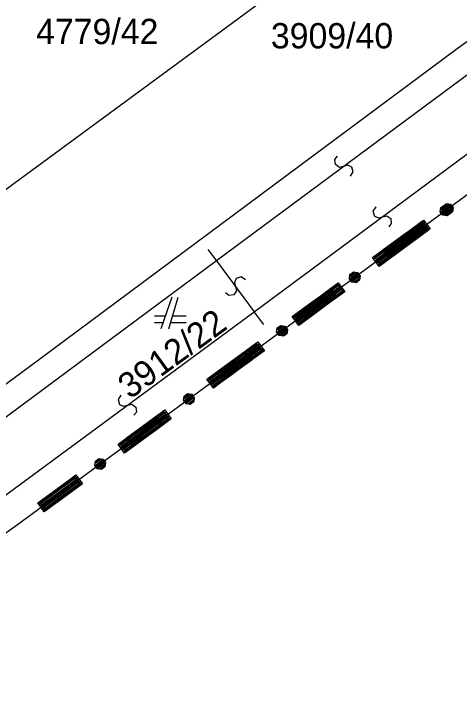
# Model space of a CAD drawing. Extents: x -266179 to -264727, y -1243225 to -1241702.
# Drawn here: x -265199.76 to -265171.61, y -1242850.11 to -1242805.99 of the extents above; entities that cross this region are included whole.
import ezdxf

# ---------------------------------------------------------------- set-up
doc = ezdxf.new("R2010")
doc.units = 0
for name, color, linetype in [('Vrstva 1', 7, 'Continuous'), ('Vrstva 19', 7, 'Continuous'), ('Vrstva 2', 7, 'Continuous'), ('Vrstva 21', 7, 'Continuous')]:
    doc.layers.add(name, color=color, linetype=linetype)

msp = doc.modelspace()

# ---------------------------------------------------------------- linework, layer by layer
at = {"layer": 'Vrstva 1'}
for p, q in [((-265203.44, -1242819.41), (-265176.4, -1242799.52)), ((-265170.69, -1242807.43), (-265171.73, -1242808.19)), ((-265171.73, -1242808.19), (-265198.21, -1242827.87)), ((-265167.21, -1242814.57), (-265177.56, -1242822.17)), ((-265177.56, -1242822.17), (-265183.44, -1242826.49)), ((-265189.77, -1242823.89), (-265190.47, -1242825.89)), ((-265189.97, -1242825.89), (-265189.37, -1242823.89)), ((-265190.19, -1242825.09), (-265190.87, -1242825.09)), ((-265188.87, -1242825.09), (-265189.73, -1242825.09)), ((-265190.87, -1242825.49), (-265190.33, -1242825.49)), ((-265189.85, -1242825.49), (-265188.87, -1242825.49)), ((-265183.44, -1242826.49), (-265199.54, -1242838.27)), ((-265198.21, -1242827.87), (-265226.94, -1242849.13)), ((-265199.54, -1242838.27), (-265215.83, -1242850.11))]:
    msp.add_line(p, q, dxfattribs=at)
at = {"layer": 'Vrstva 19'}
for p, q in [((-265167.21, -1242814.57), (-265177.56, -1242822.17)), ((-265177.56, -1242822.17), (-265183.44, -1242826.49)), ((-265183.44, -1242826.49), (-265199.54, -1242838.27)), ((-265199.54, -1242838.27), (-265215.83, -1242850.11))]:
    msp.add_line(p, q, dxfattribs=at)
for points in [[(-265172.155, -1242818.598), (-265172.373, -1242818.758), (-265172.638, -1242818.717), (-265172.798, -1242818.5), (-265172.757, -1242818.234), (-265172.54, -1242818.074), (-265172.274, -1242818.115), (-265172.114, -1242818.333), (-265172.155, -1242818.598), (-265172.187, -1242818.572), (-265172.38, -1242818.714), (-265172.492, -1242818.697), (-265172.17, -1242818.46), (-265172.153, -1242818.348), (-265172.604, -1242818.68), (-265172.651, -1242818.615), (-265172.2, -1242818.284), (-265172.247, -1242818.219), (-265172.699, -1242818.551), (-265172.746, -1242818.486), (-265172.295, -1242818.155), (-265172.406, -1242818.138), (-265172.729, -1242818.374), (-265172.712, -1242818.262), (-265172.518, -1242818.12)], [(-265172.027, -1242818.504), (-265172.244, -1242818.664), (-265172.51, -1242818.623), (-265172.67, -1242818.405), (-265172.629, -1242818.14), (-265172.411, -1242817.98), (-265172.146, -1242818.021), (-265171.986, -1242818.238), (-265172.027, -1242818.504), (-265172.058, -1242818.478), (-265172.252, -1242818.62), (-265172.364, -1242818.602), (-265172.041, -1242818.366), (-265172.024, -1242818.254), (-265172.475, -1242818.585), (-265172.523, -1242818.521), (-265172.071, -1242818.189), (-265172.119, -1242818.125), (-265172.57, -1242818.456), (-265172.617, -1242818.392), (-265172.166, -1242818.06), (-265172.278, -1242818.043), (-265172.6, -1242818.28), (-265172.583, -1242818.168), (-265172.39, -1242818.026)], [(-265173.572, -1242819.676), (-265174.596, -1242820.428), (-265175.619, -1242821.179), (-265175.99, -1242821.452), (-265176.404, -1242820.887), (-265175.381, -1242820.136), (-265174.357, -1242819.384), (-265173.986, -1242819.112), (-265173.572, -1242819.676), (-265173.67, -1242819.661), (-265174.693, -1242820.413), (-265175.717, -1242821.164), (-265175.991, -1242821.366), (-265176.039, -1242821.301), (-265175.015, -1242820.549), (-265173.991, -1242819.798), (-265173.717, -1242819.596), (-265173.765, -1242819.532), (-265174.788, -1242820.284), (-265175.812, -1242821.035), (-265176.086, -1242821.237), (-265176.133, -1242821.172), (-265175.11, -1242820.42), (-265174.086, -1242819.669), (-265173.812, -1242819.467), (-265173.859, -1242819.403), (-265174.883, -1242820.155), (-265175.907, -1242820.906), (-265176.181, -1242821.108), (-265176.228, -1242821.043), (-265175.204, -1242820.291), (-265174.181, -1242819.54), (-265173.907, -1242819.338), (-265173.954, -1242819.274), (-265174.978, -1242820.026), (-265176.001, -1242820.777), (-265176.275, -1242820.979), (-265176.323, -1242820.914), (-265175.299, -1242820.162), (-265174.275, -1242819.411), (-265174.001, -1242819.21)], [(-265173.444, -1242819.582), (-265174.467, -1242820.333), (-265175.491, -1242821.085), (-265175.862, -1242821.357), (-265176.276, -1242820.793), (-265175.252, -1242820.041), (-265174.229, -1242819.29), (-265173.858, -1242819.017), (-265173.444, -1242819.582), (-265173.541, -1242819.567), (-265174.565, -1242820.318), (-265175.589, -1242821.07), (-265175.863, -1242821.271), (-265175.91, -1242821.207), (-265174.886, -1242820.455), (-265173.863, -1242819.703), (-265173.589, -1242819.502), (-265173.636, -1242819.438), (-265174.66, -1242820.189), (-265175.683, -1242820.941), (-265175.957, -1242821.142), (-265176.005, -1242821.078), (-265174.981, -1242820.326), (-265173.957, -1242819.574), (-265173.683, -1242819.373), (-265173.731, -1242819.309), (-265174.754, -1242820.06), (-265175.778, -1242820.812), (-265176.052, -1242821.013), (-265176.099, -1242820.949), (-265175.076, -1242820.197), (-265174.052, -1242819.445), (-265173.778, -1242819.244), (-265173.826, -1242819.18), (-265174.849, -1242819.931), (-265175.873, -1242820.683), (-265176.147, -1242820.884), (-265176.194, -1242820.82), (-265175.171, -1242820.068), (-265174.147, -1242819.316), (-265173.873, -1242819.115)], [(-265174.247, -1242820.171), (-265175.27, -1242820.923), (-265176.294, -1242821.675), (-265176.665, -1242821.947), (-265177.079, -1242821.383), (-265176.055, -1242820.631), (-265175.032, -1242819.879), (-265174.661, -1242819.607), (-265174.247, -1242820.171), (-265174.328, -1242820.144), (-265175.352, -1242820.896), (-265176.376, -1242821.648), (-265176.65, -1242821.849), (-265176.697, -1242821.785), (-265175.673, -1242821.033), (-265174.65, -1242820.281), (-265174.376, -1242820.08), (-265174.423, -1242820.016), (-265175.447, -1242820.767), (-265176.47, -1242821.519), (-265176.744, -1242821.72), (-265176.792, -1242821.656), (-265175.768, -1242820.904), (-265174.744, -1242820.152), (-265174.47, -1242819.951), (-265174.518, -1242819.887), (-265175.541, -1242820.638), (-265176.565, -1242821.39), (-265176.839, -1242821.591), (-265176.886, -1242821.527), (-265175.863, -1242820.775), (-265174.839, -1242820.023), (-265174.565, -1242819.822), (-265174.612, -1242819.758), (-265175.636, -1242820.509), (-265176.66, -1242821.261), (-265176.934, -1242821.462), (-265176.981, -1242821.398), (-265175.958, -1242820.646), (-265174.934, -1242819.894), (-265174.66, -1242819.693)], [(-265177.908, -1242822.822), (-265178.125, -1242822.982), (-265178.391, -1242822.942), (-265178.551, -1242822.724), (-265178.51, -1242822.458), (-265178.292, -1242822.299), (-265178.027, -1242822.339), (-265177.867, -1242822.557), (-265177.908, -1242822.822), (-265177.939, -1242822.796), (-265178.133, -1242822.938), (-265178.245, -1242822.921), (-265177.922, -1242822.684), (-265177.905, -1242822.572), (-265178.356, -1242822.904), (-265178.404, -1242822.839), (-265177.952, -1242822.508), (-265178, -1242822.444), (-265178.451, -1242822.775), (-265178.498, -1242822.711), (-265178.047, -1242822.379), (-265178.159, -1242822.362), (-265178.481, -1242822.599), (-265178.464, -1242822.487), (-265178.271, -1242822.345)], [(-265178.843, -1242823.548), (-265179.867, -1242824.3), (-265180.89, -1242825.052), (-265181.261, -1242825.324), (-265181.675, -1242824.76), (-265180.652, -1242824.008), (-265179.628, -1242823.256), (-265179.257, -1242822.984), (-265178.843, -1242823.548), (-265178.925, -1242823.521), (-265179.948, -1242824.273), (-265180.972, -1242825.025), (-265181.246, -1242825.226), (-265181.294, -1242825.162), (-265180.27, -1242824.41), (-265179.246, -1242823.658), (-265178.972, -1242823.457), (-265179.02, -1242823.393), (-265180.043, -1242824.144), (-265181.067, -1242824.896), (-265181.341, -1242825.097), (-265181.388, -1242825.033), (-265180.365, -1242824.281), (-265179.341, -1242823.529), (-265179.067, -1242823.328), (-265179.114, -1242823.264), (-265180.138, -1242824.015), (-265181.162, -1242824.767), (-265181.436, -1242824.968), (-265181.483, -1242824.904), (-265180.459, -1242824.152), (-265179.436, -1242823.4), (-265179.162, -1242823.199), (-265179.209, -1242823.135), (-265180.233, -1242823.886), (-265181.256, -1242824.638), (-265181.53, -1242824.839), (-265181.578, -1242824.775), (-265180.554, -1242824.023), (-265179.53, -1242823.271), (-265179.256, -1242823.07)], [(-265179.325, -1242823.9), (-265180.348, -1242824.652), (-265181.372, -1242825.404), (-265181.743, -1242825.676), (-265182.157, -1242825.112), (-265181.133, -1242824.36), (-265180.11, -1242823.608), (-265179.739, -1242823.336), (-265179.325, -1242823.9), (-265179.422, -1242823.885), (-265180.446, -1242824.637), (-265181.47, -1242825.389), (-265181.744, -1242825.59), (-265181.791, -1242825.525), (-265180.767, -1242824.774), (-265179.744, -1242824.022), (-265179.47, -1242823.821), (-265179.517, -1242823.756), (-265180.541, -1242824.508), (-265181.564, -1242825.26), (-265181.838, -1242825.461), (-265181.886, -1242825.396), (-265180.862, -1242824.645), (-265179.838, -1242823.893), (-265179.564, -1242823.692), (-265179.612, -1242823.627), (-265180.635, -1242824.379), (-265181.659, -1242825.131), (-265181.933, -1242825.332), (-265181.98, -1242825.267), (-265180.957, -1242824.516), (-265179.933, -1242823.764), (-265179.659, -1242823.563), (-265179.706, -1242823.498), (-265180.73, -1242824.25), (-265181.754, -1242825.002), (-265182.028, -1242825.203), (-265182.075, -1242825.139), (-265181.052, -1242824.387), (-265180.028, -1242823.635), (-265179.754, -1242823.434)], [(-265182.504, -1242826.199), (-265182.722, -1242826.359), (-265182.987, -1242826.319), (-265183.147, -1242826.101), (-265183.106, -1242825.835), (-265182.889, -1242825.676), (-265182.623, -1242825.716), (-265182.463, -1242825.934), (-265182.504, -1242826.199), (-265182.536, -1242826.173), (-265182.729, -1242826.315), (-265182.841, -1242826.298), (-265182.519, -1242826.061), (-265182.502, -1242825.949), (-265182.953, -1242826.281), (-265183, -1242826.216), (-265182.549, -1242825.885), (-265182.596, -1242825.821), (-265183.048, -1242826.152), (-265183.095, -1242826.088), (-265182.644, -1242825.756), (-265182.755, -1242825.739), (-265183.078, -1242825.976), (-265183.061, -1242825.864), (-265182.867, -1242825.722)], [(-265183.921, -1242827.277), (-265184.945, -1242828.029), (-265185.968, -1242828.781), (-265186.339, -1242829.053), (-265186.753, -1242828.489), (-265185.73, -1242827.737), (-265184.706, -1242826.985), (-265184.335, -1242826.713), (-265183.921, -1242827.277), (-265184.019, -1242827.262), (-265185.042, -1242828.014), (-265186.066, -1242828.766), (-265186.34, -1242828.967), (-265186.388, -1242828.902), (-265185.364, -1242828.151), (-265184.34, -1242827.399), (-265184.066, -1242827.198), (-265184.114, -1242827.133), (-265185.137, -1242827.885), (-265186.161, -1242828.637), (-265186.435, -1242828.838), (-265186.482, -1242828.773), (-265185.459, -1242828.022), (-265184.435, -1242827.27), (-265184.161, -1242827.069), (-265184.208, -1242827.004), (-265185.232, -1242827.756), (-265186.256, -1242828.508), (-265186.53, -1242828.709), (-265186.577, -1242828.644), (-265185.553, -1242827.893), (-265184.53, -1242827.141), (-265184.256, -1242826.94), (-265184.303, -1242826.875), (-265185.327, -1242827.627), (-265186.35, -1242828.379), (-265186.624, -1242828.58), (-265186.672, -1242828.516), (-265185.648, -1242827.764), (-265184.624, -1242827.012), (-265184.35, -1242826.811)], [(-265184.726, -1242827.866), (-265185.751, -1242828.616), (-265186.776, -1242829.365), (-265187.147, -1242829.637), (-265187.56, -1242829.072), (-265186.535, -1242828.322), (-265185.51, -1242827.572), (-265185.139, -1242827.301), (-265184.726, -1242827.866), (-265184.807, -1242827.839), (-265185.833, -1242828.589), (-265186.858, -1242829.338), (-265187.132, -1242829.539), (-265187.179, -1242829.474), (-265186.154, -1242828.725), (-265185.129, -1242827.975), (-265184.855, -1242827.774), (-265184.902, -1242827.71), (-265185.927, -1242828.459), (-265186.952, -1242829.209), (-265187.227, -1242829.41), (-265187.274, -1242829.345), (-265186.249, -1242828.596), (-265185.223, -1242827.846), (-265184.949, -1242827.645), (-265184.996, -1242827.581), (-265186.021, -1242828.33), (-265187.047, -1242829.08), (-265187.321, -1242829.281), (-265187.368, -1242829.216), (-265186.343, -1242828.466), (-265185.318, -1242827.717), (-265185.043, -1242827.516), (-265185.091, -1242827.451), (-265186.116, -1242828.201), (-265187.141, -1242828.951), (-265187.415, -1242829.151), (-265187.463, -1242829.087), (-265186.438, -1242828.337), (-265185.412, -1242827.588), (-265185.138, -1242827.387)], [(-265188.392, -1242830.51), (-265188.61, -1242830.669), (-265188.875, -1242830.628), (-265189.035, -1242830.41), (-265188.994, -1242830.144), (-265188.776, -1242829.985), (-265188.51, -1242830.026), (-265188.351, -1242830.244), (-265188.392, -1242830.51), (-265188.424, -1242830.483), (-265188.617, -1242830.625), (-265188.729, -1242830.608), (-265188.406, -1242830.372), (-265188.389, -1242830.26), (-265188.841, -1242830.59), (-265188.888, -1242830.526), (-265188.436, -1242830.195), (-265188.483, -1242830.131), (-265188.935, -1242830.461), (-265188.983, -1242830.397), (-265188.531, -1242830.066), (-265188.642, -1242830.049), (-265188.965, -1242830.285), (-265188.948, -1242830.173), (-265188.754, -1242830.031)], [(-265189.811, -1242831.585), (-265190.836, -1242832.334), (-265191.861, -1242833.084), (-265192.233, -1242833.356), (-265192.646, -1242832.791), (-265191.621, -1242832.041), (-265190.596, -1242831.291), (-265190.224, -1242831.02), (-265189.811, -1242831.585), (-265189.909, -1242831.57), (-265190.934, -1242832.319), (-265191.959, -1242833.069), (-265192.234, -1242833.27), (-265192.281, -1242833.205), (-265191.256, -1242832.455), (-265190.231, -1242831.706), (-265189.956, -1242831.505), (-265190.003, -1242831.44), (-265191.028, -1242832.19), (-265192.054, -1242832.94), (-265192.328, -1242833.14), (-265192.375, -1242833.076), (-265191.35, -1242832.326), (-265190.325, -1242831.576), (-265190.051, -1242831.376), (-265190.098, -1242831.311), (-265191.123, -1242832.061), (-265192.148, -1242832.811), (-265192.422, -1242833.011), (-265192.47, -1242832.947), (-265191.445, -1242832.197), (-265190.419, -1242831.447), (-265190.145, -1242831.247), (-265190.192, -1242831.182), (-265191.217, -1242831.932), (-265192.242, -1242832.681), (-265192.517, -1242832.882), (-265192.564, -1242832.817), (-265191.539, -1242832.068), (-265190.514, -1242831.318), (-265190.239, -1242831.117)], [(-265190.334, -1242831.969), (-265191.359, -1242832.719), (-265192.384, -1242833.469), (-265192.756, -1242833.74), (-265193.169, -1242833.175), (-265192.144, -1242832.426), (-265191.119, -1242831.676), (-265190.747, -1242831.404), (-265190.334, -1242831.969), (-265190.416, -1242831.943), (-265191.441, -1242832.692), (-265192.466, -1242833.442), (-265192.741, -1242833.643), (-265192.788, -1242833.578), (-265191.763, -1242832.828), (-265190.738, -1242832.079), (-265190.463, -1242831.878), (-265190.51, -1242831.813), (-265191.535, -1242832.563), (-265192.561, -1242833.313), (-265192.835, -1242833.513), (-265192.882, -1242833.449), (-265191.857, -1242832.699), (-265190.832, -1242831.949), (-265190.558, -1242831.749), (-265190.605, -1242831.684), (-265191.63, -1242832.434), (-265192.655, -1242833.184), (-265192.929, -1242833.384), (-265192.977, -1242833.32), (-265191.952, -1242832.57), (-265190.926, -1242831.82), (-265190.652, -1242831.62), (-265190.699, -1242831.555), (-265191.724, -1242832.305), (-265192.749, -1242833.054), (-265193.024, -1242833.255), (-265193.071, -1242833.19), (-265192.046, -1242832.441), (-265191.021, -1242831.691), (-265190.746, -1242831.49)], [(-265194, -1242834.613), (-265194.218, -1242834.773), (-265194.484, -1242834.732), (-265194.643, -1242834.514), (-265194.602, -1242834.248), (-265194.384, -1242834.089), (-265194.119, -1242834.13), (-265193.959, -1242834.348), (-265194, -1242834.613), (-265194.032, -1242834.587), (-265194.226, -1242834.729), (-265194.338, -1242834.711), (-265194.015, -1242834.475), (-265193.997, -1242834.363), (-265194.449, -1242834.694), (-265194.497, -1242834.629), (-265194.045, -1242834.299), (-265194.092, -1242834.234), (-265194.544, -1242834.565), (-265194.591, -1242834.5), (-265194.139, -1242834.17), (-265194.251, -1242834.152), (-265194.574, -1242834.388), (-265194.556, -1242834.277), (-265194.363, -1242834.135)], [(-265195.42, -1242835.688), (-265196.445, -1242836.438), (-265197.47, -1242837.188), (-265197.841, -1242837.459), (-265198.254, -1242836.894), (-265197.229, -1242836.144), (-265196.204, -1242835.395), (-265195.833, -1242835.123), (-265195.42, -1242835.688), (-265195.517, -1242835.673), (-265196.542, -1242836.423), (-265197.568, -1242837.172), (-265197.842, -1242837.373), (-265197.889, -1242837.309), (-265196.864, -1242836.559), (-265195.839, -1242835.809), (-265195.565, -1242835.609), (-265195.612, -1242835.544), (-265196.637, -1242836.294), (-265197.662, -1242837.043), (-265197.937, -1242837.244), (-265197.984, -1242837.179), (-265196.959, -1242836.43), (-265195.933, -1242835.68), (-265195.659, -1242835.479), (-265195.706, -1242835.415), (-265196.731, -1242836.164), (-265197.757, -1242836.914), (-265198.031, -1242837.115), (-265198.078, -1242837.05), (-265197.053, -1242836.301), (-265196.028, -1242835.551), (-265195.753, -1242835.35), (-265195.801, -1242835.286), (-265196.826, -1242836.035), (-265197.851, -1242836.785), (-265198.125, -1242836.986), (-265198.173, -1242836.921), (-265197.147, -1242836.171), (-265196.122, -1242835.422), (-265195.848, -1242835.221)]]:
    msp.add_lwpolyline(points, dxfattribs=at)
at = {"layer": 'Vrstva 2'}
for p, q in [((-265170.83, -1242809.64), (-265186.95, -1242821.6)), ((-265184.56, -1242824.81), (-265168.38, -1242812.82)), ((-265187.49, -1242820.87), (-265186.95, -1242821.6)), ((-265186.95, -1242821.6), (-265202.91, -1242833.43)), ((-265186.95, -1242821.6), (-265184.56, -1242824.81)), ((-265200.61, -1242836.64), (-265184.56, -1242824.81)), ((-265183.95, -1242825.62), (-265184.56, -1242824.81))]:
    msp.add_line(p, q, dxfattribs=at)
for points in [[(-265178.483, -1242816.252), (-265178.3, -1242815.979), (-265178.39, -1242815.673), (-265178.652, -1242815.555), (-265179.172, -1242815.693), (-265179.431, -1242815.511), (-265179.464, -1242815.199), (-265179.297, -1242814.988)], [(-265176.877, -1242818.183), (-265177.06, -1242818.456), (-265176.97, -1242818.762), (-265176.708, -1242818.88), (-265176.188, -1242818.743), (-265175.929, -1242818.924), (-265175.896, -1242819.236), (-265176.063, -1242819.447)], [(-265185.123, -1242822.797), (-265185.397, -1242822.614), (-265185.703, -1242822.705), (-265185.82, -1242822.967), (-265185.682, -1242823.487), (-265185.863, -1242823.747), (-265186.175, -1242823.779), (-265186.387, -1242823.613)], [(-265192.99, -1242830.092), (-265193.174, -1242830.364), (-265193.085, -1242830.671), (-265192.824, -1242830.789), (-265192.302, -1242830.653), (-265192.044, -1242830.836), (-265192.013, -1242831.148), (-265192.18, -1242831.358)]]:
    msp.add_lwpolyline(points, dxfattribs=at)
at = {"layer": 'Vrstva 21'}
for p, q in [((-265167.21, -1242814.57), (-265177.56, -1242822.17)), ((-265177.56, -1242822.17), (-265183.44, -1242826.49)), ((-265183.44, -1242826.49), (-265199.54, -1242838.27)), ((-265199.54, -1242838.27), (-265215.83, -1242850.11))]:
    msp.add_line(p, q, dxfattribs=at)

# ---------------------------------------------------------------- texts
at = {"layer": 'Vrstva 1'}
for s, p in [('4779/42', (-265198.357, -1242807.9)), ('3909/40', (-265183.512, -1242808.17))]:
    msp.add_text(s, height=1.6, dxfattribs=at).set_placement(p)
msp.add_text('3912/22', height=1.6, rotation=35.9817, dxfattribs=at).set_placement((-265192.427, -1242830.38))

doc.saveas('drawing.dxf')
